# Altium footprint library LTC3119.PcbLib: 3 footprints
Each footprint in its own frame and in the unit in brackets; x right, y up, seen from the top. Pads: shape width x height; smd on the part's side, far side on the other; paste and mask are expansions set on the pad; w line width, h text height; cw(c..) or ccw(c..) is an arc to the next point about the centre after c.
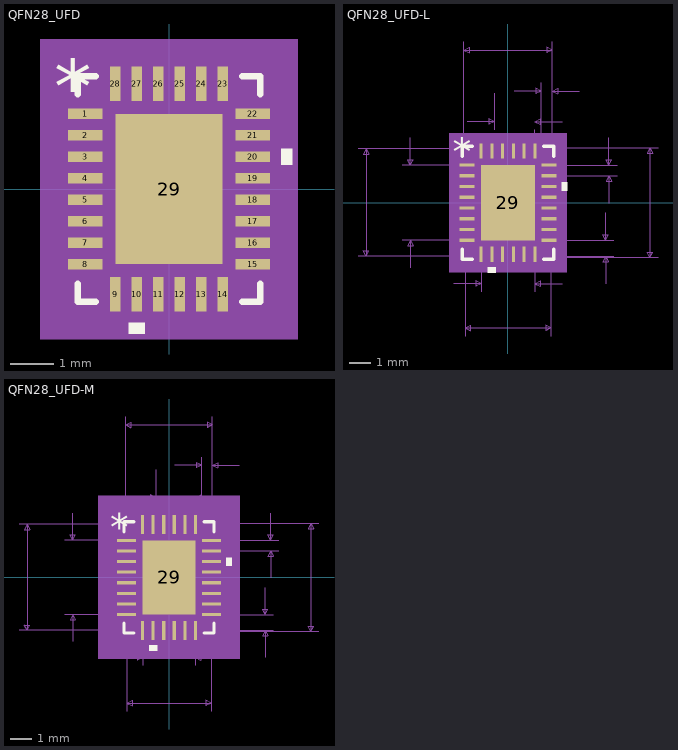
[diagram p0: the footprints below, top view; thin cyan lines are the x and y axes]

## QFN28_UFD [mm]
pads (29):
  rect 0.805x0.25 smd: 1(-1.952,1.75) 2(-1.952,1.25) 3(-1.952,0.75) 4(-1.952,0.25) 5(-1.952,-0.25) 6(-1.952,-0.75) 7(-1.952,-1.25) 8(-1.952,-1.75) 15(1.952,-1.75) 16(1.952,-1.25) 17(1.952,-0.75) 18(1.952,-0.25) 19(1.952,0.25) 20(1.952,0.75) 21(1.952,1.25) 22(1.952,1.75)
  rect 0.25x0.805 smd: 9(-1.25,-2.452) 10(-0.75,-2.452) 11(-0.25,-2.452) 12(0.25,-2.452) 13(0.75,-2.452) 14(1.25,-2.452) 23(1.25,2.452) 24(0.75,2.452) 25(0.25,2.452) 26(-0.25,2.452) 27(-0.75,2.452) 28(-1.25,2.452)
  rect 2.5x3.5 smd paste+0 mask+0: 29(0,0)
Top Overlay:
  region: 2.609,0.941 2.863,0.941 2.863,0.56 2.609,0.56
  region: -0.56,-3.109 -0.941,-3.109 -0.941,-3.363 -0.56,-3.363
  lines w0.152: -2.127,-2.208 -2.127,-2.627 -1.708,-2.627 ; -2.127,2.208 -2.127,2.627 -1.708,2.627 ; 1.708,-2.627 2.127,-2.627 2.127,-2.208 ; 1.708,2.627 2.127,2.627 2.127,2.208
  text "*" at -2.672,1.746 h1.27
Mechanical 5:
  region: 2.99,-3.49 -2.99,-3.49 -2.99,3.49 2.99,3.49
Mechanical 13:
  lines w0.025: -2,1.23 -0.73,2.5 ; -2.05,-1.875 -2,-1.875 -2,-1.625 -2.05,-1.625 -2.05,-1.875 ; -2.05,-1.375 -2,-1.375 -2,-1.125 -2.05,-1.125 -2.05,-1.375 ; -2.05,-0.875 -2,-0.875 -2,-0.625 -2.05,-0.625 -2.05,-0.875 ; -2.05,-0.375 -2,-0.375 -2,-0.125 -2.05,-0.125 -2.05,-0.375 ; -2.05,0.125 -2,0.125 -2,0.375 -2.05,0.375 -2.05,0.125 ; -2.05,0.625 -2,0.625 -2,0.875 -2.05,0.875 -2.05,0.625 ; -2.05,1.125 -2,1.125 -2,1.375 -2.05,1.375 -2.05,1.125 ; -2.05,1.625 -2,1.625 -2,1.875 -2.05,1.875 -2.05,1.625 ; -2,-2.5 -2,2.5 2,2.5 2,-2.5 -2,-2.5 ; -1.375,-2.55 -1.125,-2.55 -1.125,-2.5 -1.375,-2.5 -1.375,-2.55 ; -1.375,2.5 -1.375,2.55 -1.125,2.55 -1.125,2.5 -1.375,2.5 ; -0.875,-2.55 -0.625,-2.55 -0.625,-2.5 -0.875,-2.5 -0.875,-2.55 ; -0.875,2.5 -0.875,2.55 -0.625,2.55 -0.625,2.5 -0.875,2.5 ; -0.375,-2.55 -0.125,-2.55 -0.125,-2.5 -0.375,-2.5 -0.375,-2.55 ; -0.375,2.5 -0.375,2.55 -0.125,2.55 -0.125,2.5 -0.375,2.5 ; 0.125,-2.55 0.375,-2.55 0.375,-2.5 0.125,-2.5 0.125,-2.55 ; 0.125,2.5 0.125,2.55 0.375,2.55 0.375,2.5 0.125,2.5 ; 0.625,-2.55 0.875,-2.55 0.875,-2.5 0.625,-2.5 0.625,-2.55 ; 0.625,2.5 0.625,2.55 0.875,2.55 0.875,2.5 0.625,2.5 ; 1.125,-2.55 1.375,-2.55 1.375,-2.5 1.125,-2.5 1.125,-2.55 ; 1.125,2.5 1.125,2.55 1.375,2.55 1.375,2.5 1.125,2.5 ; 2,-1.875 2.05,-1.875 2.05,-1.625 2,-1.625 2,-1.875 ; 2,-1.375 2.05,-1.375 2.05,-1.125 2,-1.125 2,-1.375 ; 2,-0.875 2.05,-0.875 2.05,-0.625 2,-0.625 2,-0.875 ; 2,-0.375 2.05,-0.375 2.05,-0.125 2,-0.125 2,-0.375 ; 2,0.125 2.05,0.125 2.05,0.375 2,0.375 2,0.125 ; 2,0.625 2.05,0.625 2.05,0.875 2,0.875 2,0.625 ; 2,1.125 2.05,1.125 2.05,1.375 2,1.375 2,1.125 ; 2,1.625 2.05,1.625 2.05,1.875 2,1.875 2,1.625
  text "*" at -2.672,1.746 h1.27
Mechanical 15:
  region: -1.5,-2.754 -2.254,-2.754 -2.254,-2 -2.504,-2 -2.504,2 -2.254,2 -2.254,2.754 -1.5,2.754 -1.5,3.004 1.5,3.004 1.5,2.754 2.254,2.754 2.254,2 2.504,2 2.504,-2 2.254,-2 2.254,-2.754 1.5,-2.754 1.5,-3.004 -1.5,-3.004
  lines w0.152: -2.504,-2 -2.504,2 -2.254,2 -2.254,2.754 -1.5,2.754 -1.5,3.004 1.5,3.004 1.5,2.754 2.254,2.754 2.254,2 2.504,2 2.504,-2 2.254,-2 2.254,-2.754 1.5,-2.754 1.5,-3.004 -1.5,-3.004 -1.5,-2.754 -2.254,-2.754 -2.254,-2 -2.504,-2

## QFN28_UFD-L [mm]
pads (29):
  rect 0.703x0.148 smd paste+0 mask+0: 1(-1.902,1.75) 2(-1.902,1.25) 3(-1.902,0.75) 4(-1.902,0.25) 5(-1.902,-0.25) 6(-1.902,-0.75) 7(-1.902,-1.25) 8(-1.902,-1.75) 15(1.902,-1.75) 16(1.902,-1.25) 17(1.902,-0.75) 18(1.902,-0.25) 19(1.902,0.25) 20(1.902,0.75) 21(1.902,1.25) 22(1.902,1.75)
  rect 0.148x0.703 smd paste+0 mask+0: 9(-1.25,-2.402) 10(-0.75,-2.402) 11(-0.25,-2.402) 12(0.25,-2.402) 13(0.75,-2.402) 14(1.25,-2.402) 23(1.25,2.402) 24(0.75,2.402) 25(0.25,2.402) 26(-0.25,2.402) 27(-0.75,2.402) 28(-1.25,2.402)
  rect 2.5x3.5 smd paste+0 mask+0: 29(0,0)
Top Overlay:
  region: -0.56,-3.007 -0.941,-3.007 -0.941,-3.261 -0.56,-3.261
  region: 2.507,0.941 2.761,0.941 2.761,0.56 2.507,0.56
  lines w0.152: -2.127,-2.157 -2.127,-2.627 -1.657,-2.627 ; -2.127,2.157 -2.127,2.627 -1.657,2.627 ; 1.657,-2.627 2.127,-2.627 2.127,-2.157 ; 1.657,2.627 2.127,2.627 2.127,2.157
  text "*" at -2.571,1.746 h1.27
Mechanical 5:
  region: 2.736,-3.236 -2.736,-3.236 -2.736,3.236 2.736,3.236
Mechanical 7:
  lines w0.025: -6.978,-2.5 2,-2.5 ; -6.978,2.5 2,2.5 2,-6.208 ; -4.921,-1.75 -1.25,-1.75 -1.25,-4.151 ; -4.921,1.75 -1.25,1.75 ; -4.54,-3.02 -4.54,-1.75 ; -4.54,3.02 -4.54,1.75 ; -2.52,-3.77 -1.25,-3.77 ; -2.05,1.75 -2.05,7.478 ; -2,-6.208 -2,2.5 ; -1.905,3.77 -0.635,3.77 ; -0.635,3.389 -0.635,5.08 ; 0.28,5.192 1.55,5.192 ; 1.25,-4.151 1.25,-1.75 ; 1.25,-2.55 6.978,-2.55 ; 1.25,-2.5 4.921,-2.5 ; 1.25,1.75 1.25,3.389 ; 1.25,2.55 6.978,2.55 ; 1.55,1.75 1.55,5.573 ; 1.902,1.25 5.073,1.25 ; 1.902,1.75 5.073,1.75 ; 2,-1.75 4.921,-1.75 ; 2.05,5.573 2.05,1.75 2.05,7.478 ; 2.52,-3.77 1.25,-3.77 ; 2.52,3.77 1.25,3.77 ; 3.32,5.192 2.05,5.192 ; 4.54,-3.77 4.54,-2.5 ; 4.54,-0.48 4.54,-1.75 ; 4.692,-0.02 4.692,1.25 ; 4.692,3.02 4.692,1.75 ; -6.597,-2.5 -6.597,2.5 ; -6.597,-2.5 -6.724,-2.246 -6.47,-2.246 -6.597,-2.5 ; -6.597,2.5 -6.724,2.246 -6.47,2.246 -6.597,2.5 ; -4.54,-1.75 -4.667,-2.004 -4.413,-2.004 -4.54,-1.75 ; -4.54,1.75 -4.667,2.004 -4.413,2.004 -4.54,1.75 ; -2.05,7.097 2.05,7.097 ; -2.05,7.097 -1.796,7.224 -1.796,6.97 -2.05,7.097 ; -2,-5.827 2,-5.827 ; -2,-5.827 -1.746,-5.7 -1.746,-5.954 -2,-5.827 ; -1.25,-3.77 -1.504,-3.643 -1.504,-3.897 -1.25,-3.77 ; -0.635,3.77 -0.889,3.897 -0.889,3.643 -0.635,3.77 ; 1.25,-3.77 1.504,-3.643 1.504,-3.897 1.25,-3.77 ; 1.25,3.77 1.504,3.897 1.504,3.643 1.25,3.77 ; 1.55,5.192 1.296,5.319 1.296,5.065 1.55,5.192 ; 2,-5.827 1.746,-5.7 1.746,-5.954 2,-5.827 ; 2.05,5.192 2.304,5.319 2.304,5.065 2.05,5.192 ; 2.05,7.097 1.796,7.224 1.796,6.97 2.05,7.097 ; 4.54,-2.5 4.413,-2.754 4.667,-2.754 4.54,-2.5 ; 4.54,-1.75 4.413,-1.496 4.667,-1.496 4.54,-1.75 ; 4.692,1.25 4.565,0.996 4.819,0.996 4.692,1.25 ; 4.692,1.75 4.565,2.004 4.819,2.004 4.692,1.75 ; 6.597,-2.55 6.597,2.55 ; 6.597,-2.55 6.47,-2.296 6.724,-2.296 6.597,-2.55 ; 6.597,2.55 6.47,2.296 6.724,2.296 6.597,2.55
  text "Default Padstyle: RX5p84Y27p69D0T" at -10.477,-9.002 h1.27
  text "Heat Tab 1 Padstyle: RX98p43Y137p8D0T" at -11.747,-10.526 h1.27
  text "Alt 1 Padstyle: OX60Y90D30P" at -8.572,-19.67 h1.27
  text "Alt 2 Padstyle: OX90Y60D30P" at -8.572,-21.194 h1.27
  text "0.02in/0.5mm" at 2.787,1.182 h0.64
  text "0.016in/0.4mm" at -0.264,5.7 h0.64
  text "0.161in/4.1mm" at -2.064,7.605 h0.64
  text "0.201in/5.1mm" at 7.105,-0.318 h0.64
  text "0.197in/5mm" at -10.597,-0.318 h0.64
  text "0.157in/4mm" at -1.746,-6.97 h0.64
  text "0.098in/2.5mm" at -2.064,-4.913 h0.64
  text "0.138in/3.5mm" at -6.604,-0.508 h0.64
  text "-0.074in/-1.885mm" at -2.699,4.278 h0.64
  text "0.03in/0.75mm" at 2.476,-2.392 h0.64
Mechanical 13:
  lines w0.025: -2,1.23 -0.73,2.5 ; -2.05,-1.875 -2.05,-1.625 -2,-1.625 -2,-1.875 -2.05,-1.875 ; -2.05,-1.375 -2.05,-1.125 -2,-1.125 -2,-1.375 -2.05,-1.375 ; -2.05,-0.875 -2.05,-0.625 -2,-0.625 -2,-0.875 -2.05,-0.875 ; -2.05,-0.375 -2.05,-0.125 -2,-0.125 -2,-0.375 -2.05,-0.375 ; -2.05,0.125 -2.05,0.375 -2,0.375 -2,0.125 -2.05,0.125 ; -2.05,0.625 -2.05,0.875 -2,0.875 -2,0.625 -2.05,0.625 ; -2.05,1.125 -2.05,1.375 -2,1.375 -2,1.125 -2.05,1.125 ; -2.05,1.625 -2.05,1.875 -2,1.875 -2,1.625 -2.05,1.625 ; -2,-2.5 2,-2.5 2,2.5 -2,2.5 -2,-2.5 ; -1.375,-2.55 -1.375,-2.5 -1.125,-2.5 -1.125,-2.55 -1.375,-2.55 ; -1.375,2.5 -1.125,2.5 -1.125,2.55 -1.375,2.55 -1.375,2.5 ; -0.875,-2.55 -0.875,-2.5 -0.625,-2.5 -0.625,-2.55 -0.875,-2.55 ; -0.875,2.5 -0.625,2.5 -0.625,2.55 -0.875,2.55 -0.875,2.5 ; -0.375,-2.55 -0.375,-2.5 -0.125,-2.5 -0.125,-2.55 -0.375,-2.55 ; -0.375,2.5 -0.125,2.5 -0.125,2.55 -0.375,2.55 -0.375,2.5 ; 0.125,-2.55 0.125,-2.5 0.375,-2.5 0.375,-2.55 0.125,-2.55 ; 0.125,2.5 0.375,2.5 0.375,2.55 0.125,2.55 0.125,2.5 ; 0.625,-2.55 0.625,-2.5 0.875,-2.5 0.875,-2.55 0.625,-2.55 ; 0.625,2.5 0.875,2.5 0.875,2.55 0.625,2.55 0.625,2.5 ; 1.125,-2.55 1.125,-2.5 1.375,-2.5 1.375,-2.55 1.125,-2.55 ; 1.125,2.5 1.375,2.5 1.375,2.55 1.125,2.55 1.125,2.5 ; 2,-1.875 2,-1.625 2.05,-1.625 2.05,-1.875 2,-1.875 ; 2,-1.375 2,-1.125 2.05,-1.125 2.05,-1.375 2,-1.375 ; 2,-0.875 2,-0.625 2.05,-0.625 2.05,-0.875 2,-0.875 ; 2,-0.375 2,-0.125 2.05,-0.125 2.05,-0.375 2,-0.375 ; 2,0.125 2,0.375 2.05,0.375 2.05,0.125 2,0.125 ; 2,0.625 2,0.875 2.05,0.875 2.05,0.625 2,0.625 ; 2,1.125 2,1.375 2.05,1.375 2.05,1.125 2,1.125 ; 2,1.625 2,1.875 2.05,1.875 2.05,1.625 2,1.625
  text "*" at -2.571,1.746 h1.27
Mechanical 15:
  region: -1.426,-2.602 -2.102,-2.602 -2.102,-1.926 -2.355,-1.926 -2.355,1.926 -2.102,1.926 -2.102,2.602 -1.426,2.602 -1.426,2.855 1.426,2.855 1.426,2.602 2.102,2.602 2.102,1.926 2.355,1.926 2.355,-1.926 2.102,-1.926 2.102,-2.602 1.426,-2.602 1.426,-2.855 -1.426,-2.855
  lines w0.152: -2.355,-1.926 -2.102,-1.926 -2.102,-2.602 -1.426,-2.602 -1.426,-2.855 1.426,-2.855 1.426,-2.602 2.102,-2.602 2.102,-1.926 2.355,-1.926 2.355,1.926 2.102,1.926 2.102,2.602 1.426,2.602 1.426,2.855 -1.426,2.855 -1.426,2.602 -2.102,2.602 -2.102,1.926 -2.355,1.926 -2.355,-1.926
3D body: height 0.25, standoff 0, extent 0,0 0.254,0.254

## QFN28_UFD-M [mm]
pads (29):
  rect 0.906x0.148 smd paste+0 mask+0: 1(-2.003,1.75) 2(-2.003,1.25) 3(-2.003,0.75) 4(-2.003,0.25) 5(-2.003,-0.25) 6(-2.003,-0.75) 7(-2.003,-1.25) 8(-2.003,-1.75) 15(2.003,-1.75) 16(2.003,-1.25) 17(2.003,-0.75) 18(2.003,-0.25) 19(2.003,0.25) 20(2.003,0.75) 21(2.003,1.25) 22(2.003,1.75)
  rect 0.148x0.906 smd paste+0 mask+0: 9(-1.25,-2.503) 10(-0.75,-2.503) 11(-0.25,-2.503) 12(0.25,-2.503) 13(0.75,-2.503) 14(1.25,-2.503) 23(1.25,2.503) 24(0.75,2.503) 25(0.25,2.503) 26(-0.25,2.503) 27(-0.75,2.503) 28(-1.25,2.503)
  rect 2.5x3.5 smd paste+0 mask+0: 29(0,0)
Top Overlay:
  region: -0.56,-3.21 -0.941,-3.21 -0.941,-3.464 -0.56,-3.464
  region: 2.71,0.941 2.964,0.941 2.964,0.56 2.71,0.56
  lines w0.152: -2.127,-2.157 -2.127,-2.627 -1.657,-2.627 ; -2.127,2.157 -2.127,2.627 -1.657,2.627 ; 1.657,-2.627 2.127,-2.627 2.127,-2.157 ; 1.657,2.627 2.127,2.627 2.127,2.157
  text "*" at -2.774,1.746 h1.27
Mechanical 5:
  region: 3.345,-3.845 -3.345,-3.845 -3.345,3.845 3.345,3.845
Mechanical 7:
  lines w0.025: -7.079,-2.5 2,-2.5 ; -7.079,2.5 2,2.5 2,-6.309 ; -4.921,-1.75 -1.25,-1.75 -1.25,-4.151 ; -4.921,1.75 -1.25,1.75 ; -4.54,-3.02 -4.54,-1.75 ; -4.54,3.02 -4.54,1.75 ; -2.52,-3.77 -1.25,-3.77 ; -2.05,1.75 -2.05,7.579 ; -2,-6.309 -2,2.5 ; -1.905,3.77 -0.635,3.77 ; -0.635,3.389 -0.635,5.08 ; 0.28,5.293 1.55,5.293 ; 1.25,-4.151 1.25,-1.75 ; 1.25,-2.55 7.079,-2.55 ; 1.25,-2.5 4.921,-2.5 ; 1.25,1.75 1.25,3.389 ; 1.25,2.55 7.079,2.55 ; 1.55,1.75 1.55,5.674 ; 2,-1.75 4.921,-1.75 ; 2.003,1.25 5.174,1.25 ; 2.003,1.75 5.174,1.75 ; 2.05,5.674 2.05,1.75 2.05,7.579 ; 2.52,-3.77 1.25,-3.77 ; 2.52,3.77 1.25,3.77 ; 3.32,5.293 2.05,5.293 ; 4.54,-3.77 4.54,-2.5 ; 4.54,-0.48 4.54,-1.75 ; 4.793,-0.02 4.793,1.25 ; 4.793,3.02 4.793,1.75 ; -6.698,-2.5 -6.698,2.5 ; -6.698,-2.5 -6.825,-2.246 -6.571,-2.246 -6.698,-2.5 ; -6.698,2.5 -6.825,2.246 -6.571,2.246 -6.698,2.5 ; -4.54,-1.75 -4.667,-2.004 -4.413,-2.004 -4.54,-1.75 ; -4.54,1.75 -4.667,2.004 -4.413,2.004 -4.54,1.75 ; -2.05,7.198 2.05,7.198 ; -2.05,7.198 -1.796,7.325 -1.796,7.071 -2.05,7.198 ; -2,-5.928 2,-5.928 ; -2,-5.928 -1.746,-5.801 -1.746,-6.055 -2,-5.928 ; -1.25,-3.77 -1.504,-3.643 -1.504,-3.897 -1.25,-3.77 ; -0.635,3.77 -0.889,3.897 -0.889,3.643 -0.635,3.77 ; 1.25,-3.77 1.504,-3.643 1.504,-3.897 1.25,-3.77 ; 1.25,3.77 1.504,3.897 1.504,3.643 1.25,3.77 ; 1.55,5.293 1.296,5.42 1.296,5.166 1.55,5.293 ; 2,-5.928 1.746,-5.801 1.746,-6.055 2,-5.928 ; 2.05,5.293 2.304,5.42 2.304,5.166 2.05,5.293 ; 2.05,7.198 1.796,7.325 1.796,7.071 2.05,7.198 ; 4.54,-2.5 4.413,-2.754 4.667,-2.754 4.54,-2.5 ; 4.54,-1.75 4.413,-1.496 4.667,-1.496 4.54,-1.75 ; 4.793,1.25 4.666,0.996 4.92,0.996 4.793,1.25 ; 4.793,1.75 4.666,2.004 4.92,2.004 4.793,1.75 ; 6.698,-2.55 6.698,2.55 ; 6.698,-2.55 6.571,-2.296 6.825,-2.296 6.698,-2.55 ; 6.698,2.55 6.571,2.296 6.825,2.296 6.698,2.55
  text "Default Padstyle: RX5p84Y35p69D0T" at -10.477,-9.103 h1.27
  text "Heat Tab 1 Padstyle: RX98p43Y137p8D0T" at -11.747,-10.627 h1.27
  text "Alt 1 Padstyle: OX60Y90D30P" at -8.572,-19.771 h1.27
  text "Alt 2 Padstyle: OX90Y60D30P" at -8.572,-21.295 h1.27
  text "0.02in/0.5mm" at 2.888,1.182 h0.64
  text "0.016in/0.4mm" at -0.264,5.801 h0.64
  text "0.161in/4.1mm" at -2.064,7.706 h0.64
  text "0.201in/5.1mm" at 7.206,-0.318 h0.64
  text "0.197in/5mm" at -10.699,-0.318 h0.64
  text "0.157in/4mm" at -1.746,-7.071 h0.64
  text "0.098in/2.5mm" at -2.064,-4.913 h0.64
  text "0.138in/3.5mm" at -6.604,-0.508 h0.64
  text "-0.074in/-1.885mm" at -2.699,4.278 h0.64
  text "0.03in/0.75mm" at 2.476,-2.494 h0.64
Mechanical 13:
  lines w0.025: -2,1.23 -0.73,2.5 ; -2.05,-1.875 -2.05,-1.625 -2,-1.625 -2,-1.875 -2.05,-1.875 ; -2.05,-1.375 -2.05,-1.125 -2,-1.125 -2,-1.375 -2.05,-1.375 ; -2.05,-0.875 -2.05,-0.625 -2,-0.625 -2,-0.875 -2.05,-0.875 ; -2.05,-0.375 -2.05,-0.125 -2,-0.125 -2,-0.375 -2.05,-0.375 ; -2.05,0.125 -2.05,0.375 -2,0.375 -2,0.125 -2.05,0.125 ; -2.05,0.625 -2.05,0.875 -2,0.875 -2,0.625 -2.05,0.625 ; -2.05,1.125 -2.05,1.375 -2,1.375 -2,1.125 -2.05,1.125 ; -2.05,1.625 -2.05,1.875 -2,1.875 -2,1.625 -2.05,1.625 ; -2,-2.5 2,-2.5 2,2.5 -2,2.5 -2,-2.5 ; -1.375,-2.55 -1.375,-2.5 -1.125,-2.5 -1.125,-2.55 -1.375,-2.55 ; -1.375,2.5 -1.125,2.5 -1.125,2.55 -1.375,2.55 -1.375,2.5 ; -0.875,-2.55 -0.875,-2.5 -0.625,-2.5 -0.625,-2.55 -0.875,-2.55 ; -0.875,2.5 -0.625,2.5 -0.625,2.55 -0.875,2.55 -0.875,2.5 ; -0.375,-2.55 -0.375,-2.5 -0.125,-2.5 -0.125,-2.55 -0.375,-2.55 ; -0.375,2.5 -0.125,2.5 -0.125,2.55 -0.375,2.55 -0.375,2.5 ; 0.125,-2.55 0.125,-2.5 0.375,-2.5 0.375,-2.55 0.125,-2.55 ; 0.125,2.5 0.375,2.5 0.375,2.55 0.125,2.55 0.125,2.5 ; 0.625,-2.55 0.625,-2.5 0.875,-2.5 0.875,-2.55 0.625,-2.55 ; 0.625,2.5 0.875,2.5 0.875,2.55 0.625,2.55 0.625,2.5 ; 1.125,-2.55 1.125,-2.5 1.375,-2.5 1.375,-2.55 1.125,-2.55 ; 1.125,2.5 1.375,2.5 1.375,2.55 1.125,2.55 1.125,2.5 ; 2,-1.875 2,-1.625 2.05,-1.625 2.05,-1.875 2,-1.875 ; 2,-1.375 2,-1.125 2.05,-1.125 2.05,-1.375 2,-1.375 ; 2,-0.875 2,-0.625 2.05,-0.625 2.05,-0.875 2,-0.875 ; 2,-0.375 2,-0.125 2.05,-0.125 2.05,-0.375 2,-0.375 ; 2,0.125 2,0.375 2.05,0.375 2.05,0.125 2,0.125 ; 2,0.625 2,0.875 2.05,0.875 2.05,0.625 2,0.625 ; 2,1.125 2,1.375 2.05,1.375 2.05,1.125 2,1.125 ; 2,1.625 2,1.875 2.05,1.875 2.05,1.625 2,1.625
  text "*" at -2.774,1.746 h1.27
Mechanical 15:
  region: -1.832,-3.008 -2.508,-3.008 -2.508,-2.332 -2.964,-2.332 -2.964,2.332 -2.508,2.332 -2.508,3.008 -1.832,3.008 -1.832,3.464 1.832,3.464 1.832,3.008 2.508,3.008 2.508,2.332 2.964,2.332 2.964,-2.332 2.508,-2.332 2.508,-3.008 1.832,-3.008 1.832,-3.464 -1.832,-3.464
  lines w0.152: -2.964,-2.332 -2.508,-2.332 -2.508,-3.008 -1.832,-3.008 -1.832,-3.464 1.832,-3.464 1.832,-3.008 2.508,-3.008 2.508,-2.332 2.964,-2.332 2.964,2.332 2.508,2.332 2.508,3.008 1.832,3.008 1.832,3.464 -1.832,3.464 -1.832,3.008 -2.508,3.008 -2.508,2.332 -2.964,2.332 -2.964,-2.332
3D body: height 0.25, standoff 0, extent 0,0 0.254,0.254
